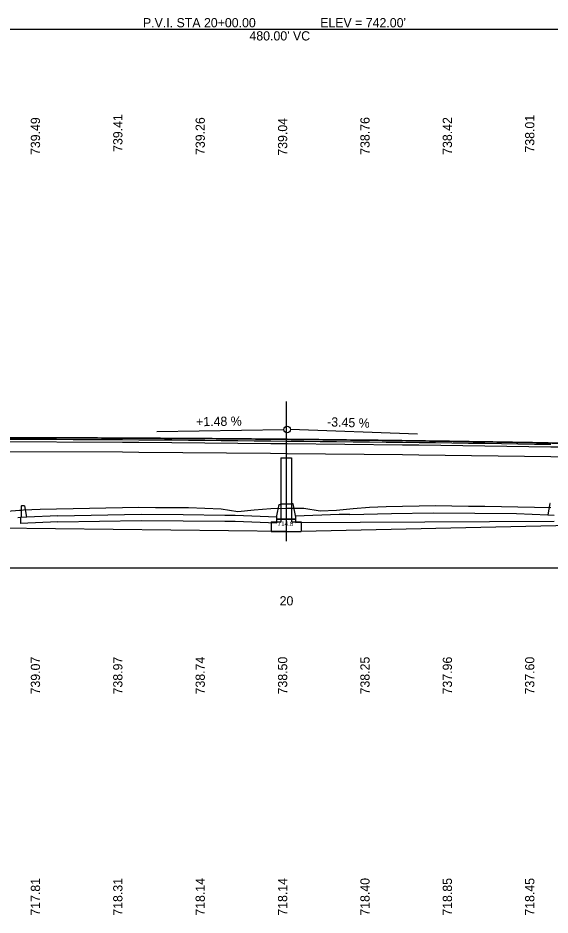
# Model space of a CAD drawing. Extents: x -434 to 1339, y -871 to 603.
# Drawn here: x 418.3 to 579.8, y -105.4 to 167 of the extents above; entities that cross this region are included whole.
import ezdxf

# ---------------------------------------------------------------- set-up
doc = ezdxf.new("R2010")
doc.units = 0
for name, color, linetype in [('BR_P_Gen_Hatch', 7, 'Continuous'), ('BR_P_Slab_Object', 7, 'Continuous'), ('BR_X_Beam_Object', 7, 'Continuous'), ('BR_X_Sub_Centerline', 7, 'Continuous'), ('BR_X_Sub_Object', 7, 'Continuous'), ('Default', 7, 'Continuous'), ('GK_Cells', 7, 'Continuous'), ('PF_P_Grade_Line', 7, 'Continuous'), ('PF_P_Sta_Elev_Text', 7, 'Continuous'), ('PF_P_Text', 7, 'Continuous'), ('PF_X_Ground_Line', 7, 'Continuous'), ('PV_P_EOP', 7, 'Continuous'), ('SC_Scratch1', 7, 'Continuous'), ('SC_Scratch2', 7, 'Continuous'), ('XS_P_Annotation', 7, 'Continuous'), ('XS_P_Barrier', 7, 'Continuous'), ('XS_P_Barrier_Surface', 7, 'Continuous'), ('XS_P_Finished_Grade', 7, 'Continuous'), ('XS_P_Finished_Grade_Seeded', 7, 'Continuous'), ('XS_P_Pavt_Surface', 7, 'Continuous'), ('XS_P_Shoulder_Surface', 7, 'Continuous'), ('XS_P_Subgrade', 7, 'Continuous'), ('XS_X_Ground_Line', 7, 'Continuous')]:
    doc.layers.add(name, color=color, linetype=linetype)

msp = doc.modelspace()

# ---------------------------------------------------------------- linework, layer by layer
at = {"layer": 'BR_P_Gen_Hatch'}
msp.add_lwpolyline([(355.72, 38.2), (400, 38.39), (405, 38.4), (410, 38.38), (450, 38.22), (454.99, 38.18), (494.99, 37.8), (499.99, 37.75), (534.99, 37.4), (539.99, 37.35), (579.99, 36.78), (584.99, 36.71), (589.99, 36.61), (624.99, 35.92), (629.98, 35.83), (634.98, 35.69), (643.57, 35.44)], dxfattribs=at)
msp.add_spline([(673, 35.8), (672.8, 35.81), (663.2, 36.07), (653.6, 36.32), (644, 36.56), (634.4, 36.79), (624.8, 37.01), (615.2, 37.23), (605.6, 37.43), (596, 37.62), (586.4, 37.81), (576.8, 37.98), (567.2, 38.15), (557.6, 38.3), (548, 38.45), (538.4, 38.59), (528.8, 38.72), (519.2, 38.83), (509.6, 38.94), (500, 39.04), (490.4, 39.13), (480.8, 39.21), (471.2, 39.28), (461.6, 39.34), (452, 39.4), (442.4, 39.44), (432.8, 39.47), (423.2, 39.5), (413.6, 39.51), (404, 39.51), (394.4, 39.51), (384.8, 39.5), (375.2, 39.47), (365.6, 39.44), (356, 39.4), (346.4, 39.34), (336.8, 39.28), (327.2, 39.21), (326.42, 39.2)], degree=3, dxfattribs=at)
at = {"layer": 'BR_P_Slab_Object'}
msp.add_lwpolyline([(355.72, 38.2), (400, 38.39), (405, 38.4), (410, 38.38), (450, 38.22), (454.99, 38.18), (494.99, 37.8), (499.99, 37.75), (534.99, 37.4), (539.99, 37.35), (579.99, 36.78), (584.99, 36.71), (589.99, 36.61), (624.99, 35.92), (629.98, 35.83), (634.98, 35.69), (643.57, 35.44)], dxfattribs=at)
at = {"layer": 'BR_X_Beam_Object'}
for points in [[(352.99, 38.18), (355, 38.19), (400, 38.39), (405, 38.4), (410, 38.38), (450, 38.22), (454.99, 38.18), (494.99, 37.8), (499.99, 37.75), (534.99, 37.4), (539.99, 37.35), (579.99, 36.78), (584.99, 36.71), (589.99, 36.61), (624.99, 35.92), (629.98, 35.83), (634.98, 35.69), (644.98, 35.4), (646.43, 35.36)], [(352.99, 35.18), (355.02, 35.19), (400.01, 35.39), (405, 35.4), (409.98, 35.38), (449.98, 35.22), (454.97, 35.18), (494.96, 34.8), (499.96, 34.75), (534.96, 34.4), (539.96, 34.35), (579.95, 33.78), (584.94, 33.71), (589.93, 33.61), (624.93, 32.92), (629.91, 32.83), (634.89, 32.69), (644.89, 32.41), (646.43, 32.36)]]:
    msp.add_lwpolyline(points, dxfattribs=at)
at = {"layer": 'BR_X_Sub_Centerline'}
msp.add_line((499.7, 50.56), (499.7, 8.12), dxfattribs=at)
at = {"layer": 'BR_X_Sub_Object'}
for p, q in [((498.11, 33.37), (498.11, 14)), ((498.11, 33.37), (501.28, 33.37)), ((501.28, 33.37), (501.28, 14)), ((495.11, 14), (495.11, 11)), ((495.11, 14), (498.11, 14)), ((501.28, 14), (504.28, 14)), ((504.28, 14), (504.28, 11)), ((495.11, 11), (504.28, 11))]:
    msp.add_line(p, q, dxfattribs=at)
at = {"layer": 'Default'}
msp.add_line((0, 0), (1050.49, 0), dxfattribs=at)
at = {"layer": 'GK_Cells'}
msp.add_line((0, 0), (1000, 0), dxfattribs=at)
at = {"layer": 'PF_P_Grade_Line'}
msp.add_spline([(260, 38.45), (269.6, 38.59), (279.2, 38.71), (288.8, 38.83), (298.4, 38.94), (308, 39.04), (317.6, 39.13), (327.2, 39.21), (336.8, 39.28), (346.4, 39.34), (356, 39.4), (365.6, 39.44), (375.2, 39.47), (384.8, 39.5), (394.4, 39.51), (404, 39.51), (413.6, 39.51), (423.2, 39.5), (432.8, 39.47), (442.4, 39.44), (452, 39.4), (461.6, 39.34), (471.2, 39.28), (480.8, 39.21), (490.4, 39.13), (500, 39.04), (509.6, 38.94), (519.2, 38.83), (528.8, 38.72), (538.4, 38.59), (548, 38.45), (557.6, 38.3), (567.2, 38.15), (576.8, 37.98), (586.4, 37.81), (596, 37.62), (605.6, 37.43), (615.2, 37.23), (624.8, 37.01), (634.4, 36.79), (644, 36.56), (653.6, 36.32), (663.2, 36.07), (672.8, 35.81), (682.4, 35.54), (692, 35.26), (701.6, 34.97), (711.2, 34.67), (720.8, 34.36), (730.4, 34.05), (740, 33.72)], degree=3, dxfattribs=at)
at = {"layer": 'PF_P_Text'}
for p, q in [((260, 163.55), (740, 163.55)), ((460.4, 41.41), (499, 41.99)), ((539.58, 40.63), (501, 41.97))]:
    msp.add_line(p, q, dxfattribs=at)
msp.add_circle((500, 42), 1, dxfattribs=at)
at = {"layer": 'PF_X_Ground_Line'}
msp.add_lwpolyline([(415, 39.11), (420, 39.09), (425, 39.07), (430, 39.05), (435, 39.03), (440, 39.01), (445, 38.99), (450, 38.97), (455, 38.93), (460, 38.88), (465, 38.84), (470, 38.79), (475, 38.74), (480, 38.69), (485, 38.64), (490, 38.6), (495, 38.55), (500, 38.5), (505, 38.45), (510, 38.4), (515, 38.35), (520, 38.3), (525, 38.25), (530, 38.2), (535, 38.15), (540, 38.1), (545, 38.03), (550, 37.96), (555, 37.89), (560, 37.82), (565, 37.75), (570, 37.67), (575, 37.6), (580, 37.53)], dxfattribs=at)
at = {"layer": 'PV_P_EOP'}
for p, q in [((518.98, 16.24), (531.62, 16.5)), ((531.62, 16.5), (544.27, 16.76)), ((544.27, 16.76), (569.57, 16.51)), ((430.44, 15.8), (455.73, 16.31)), ((455.73, 16.31), (468.38, 16.18)), ((468.38, 16.18), (481.03, 16.05))]:
    msp.add_line(p, q, dxfattribs=at)
at = {"layer": 'SC_Scratch1'}
for q in [(645.63, 14.4), (353.71, 12.7)]:
    msp.add_line((499.7, 11), q, dxfattribs=at)
at = {"layer": 'SC_Scratch2'}
for points in [[(415, 17.22), (420, 17.63), (425, 17.81), (430, 17.89), (435, 18), (440, 18.1), (445, 18.21), (450, 18.31), (455, 18.41), (460, 18.37), (465, 18.37), (470, 18.34), (475, 18.14), (480, 17.91), (485, 17.12), (490, 17.65), (495, 18.03), (500, 18.14)], [(500, 18.14), (505, 18.15), (510, 17.28), (515, 17.54), (520, 18.06), (525, 18.4), (530, 18.6), (535, 18.78), (540, 18.88), (545, 18.93), (550, 18.85), (555, 18.78), (560, 18.71), (565, 18.64), (570, 18.56), (575, 18.45), (580, 18.37)]]:
    msp.add_lwpolyline(points, dxfattribs=at)
at = {"layer": 'XS_P_Barrier'}
for p, q in [((496.88, 14.79), (496.88, 15.54)), ((502.51, 14.79), (496.88, 14.79)), ((502.51, 15.68), (502.51, 14.79))]:
    msp.add_line(p, q, dxfattribs=at)
at = {"layer": 'XS_P_Barrier_Surface'}
for p, q in [((496.88, 15.79), (497.59, 19.29)), ((497.59, 19.29), (498.11, 19.29)), ((498.11, 19.43), (501.28, 19.43)), ((498.11, 19.29), (498.11, 19.43)), ((501.81, 19.43), (501.28, 19.43)), ((502.51, 15.93), (501.81, 19.43)), ((579.72, 19.54), (579.08, 16.15)), ((579.76, 19.57), (579.72, 19.54)), ((419.38, 18.92), (419.34, 18.88)), ((419.34, 15.32), (419.34, 18.88)), ((419.38, 18.92), (420.24, 18.92)), ((419.38, 18.92), (420.13, 18.92)), ((420.28, 18.88), (420.93, 15.44)), ((496.88, 15.54), (496.88, 15.79)), ((502.51, 15.68), (502.51, 15.93))]:
    msp.add_line(p, q, dxfattribs=at)
at = {"layer": 'XS_P_Finished_Grade'}
msp.add_line((419.02, 15.3), (418.3, 15.24), dxfattribs=at)
at = {"layer": 'XS_P_Finished_Grade_Seeded'}
for p, q in [((420.95, 15.44), (419.02, 15.3)), ((579.06, 16.15), (580.99, 16))]:
    msp.add_line(p, q, dxfattribs=at)
at = {"layer": 'XS_P_Pavt_Surface'}
for p, q in [((518.98, 16.24), (531.62, 16.49)), ((531.62, 16.49), (544.27, 16.73)), ((544.27, 16.73), (569.57, 16.49)), ((430.44, 15.8), (455.73, 16.28)), ((455.73, 16.28), (468.38, 16.16)), ((468.38, 16.16), (481.03, 16.04)), ((481.03, 16.05), (484.19, 16.02)), ((518.98, 16.24), (515.81, 16.18))]:
    msp.add_line(p, q, dxfattribs=at)
at = {"layer": 'XS_P_Shoulder_Surface'}
for p, q in [((569.57, 16.51), (579.06, 16.15)), ((430.44, 15.8), (420.95, 15.44)), ((484.19, 16.02), (496.88, 15.54)), ((515.81, 16.18), (502.51, 15.68))]:
    msp.add_line(p, q, dxfattribs=at)
at = {"layer": 'XS_P_Subgrade'}
for p, q in [((419.02, 15.3), (419.02, 13.49)), ((430.44, 13.93), (419.02, 13.49)), ((430.44, 13.93), (455.73, 14.41)), ((455.73, 14.41), (468.38, 14.29)), ((468.38, 14.29), (481.03, 14.16)), ((481.03, 14.18), (484.19, 14.15)), ((484.19, 14.15), (496.88, 13.67)), ((496.88, 14.79), (502.51, 14.79)), ((496.88, 13.67), (496.88, 14.79)), ((502.51, 14.79), (502.51, 13.8)), ((502.51, 13.8), (580.99, 14.2))]:
    msp.add_line(p, q, dxfattribs=at)
at = {"layer": 'XS_X_Ground_Line'}
for p, q in [((416.22, 17.29), (419, 17.57)), ((419, 17.57), (419.34, 17.57))]:
    msp.add_line(p, q, dxfattribs=at)

# ---------------------------------------------------------------- texts
at = {"layer": 'Default'}
for s, p in [('739.07', (425, -38.43)), ('738.97', (450, -38.43)), ('738.74', (475, -38.43)), ('738.50', (500, -38.43)), ('738.25', (525, -38.43)), ('737.96', (550, -38.43)), ('737.60', (575, -38.43)), ('717.81', (425, -105.62)), ('718.31', (450, -105.62)), ('718.14', (475, -105.62)), ('718.14', (500, -105.62)), ('718.40', (525, -105.62)), ('718.85', (550, -105.62)), ('718.45', (575, -105.62))]:
    msp.add_text(s, height=2.8, rotation=90, dxfattribs=at).set_placement(p)
at = {"layer": 'PF_P_Sta_Elev_Text'}
msp.add_text('20', height=2.8, dxfattribs=at).set_placement((497.7, -11.4))
msp.add_text('20', height=2.8, dxfattribs=at).set_placement((497.7, -11.4))
at = {"layer": 'PF_P_Text'}
for s, p in [('P.V.I. STA 20+00.00', (456.22, 164.15)), ("ELEV = 742.00'", (510, 164.15)), ("480.00' VC", (488.54, 160.15))]:
    msp.add_text(s, height=2.8, dxfattribs=at).set_placement(p)
for s, rotation, p in [('739.49', 90, (425, 125.37)), ('739.41', 90, (450, 126.32)), ('739.26', 90, (475, 125.39)), ('739.04', 90, (500, 125.17)), ('738.76', 90, (525, 125.43)), ('738.42', 90, (550, 125.43)), ('738.01', 90, (575, 126.12)), ('+1.48 %', 0.8479, (472.37, 42.99)), ('-3.45 %', 358.0241, (512.08, 42.98))]:
    msp.add_text(s, height=2.8, rotation=rotation, dxfattribs=at).set_placement(p)
at = {"layer": 'XS_P_Annotation'}
msp.add_text('714.8', height=1.4, dxfattribs=at).set_placement((497.05, 12.69))

doc.saveas('drawing.dxf')
